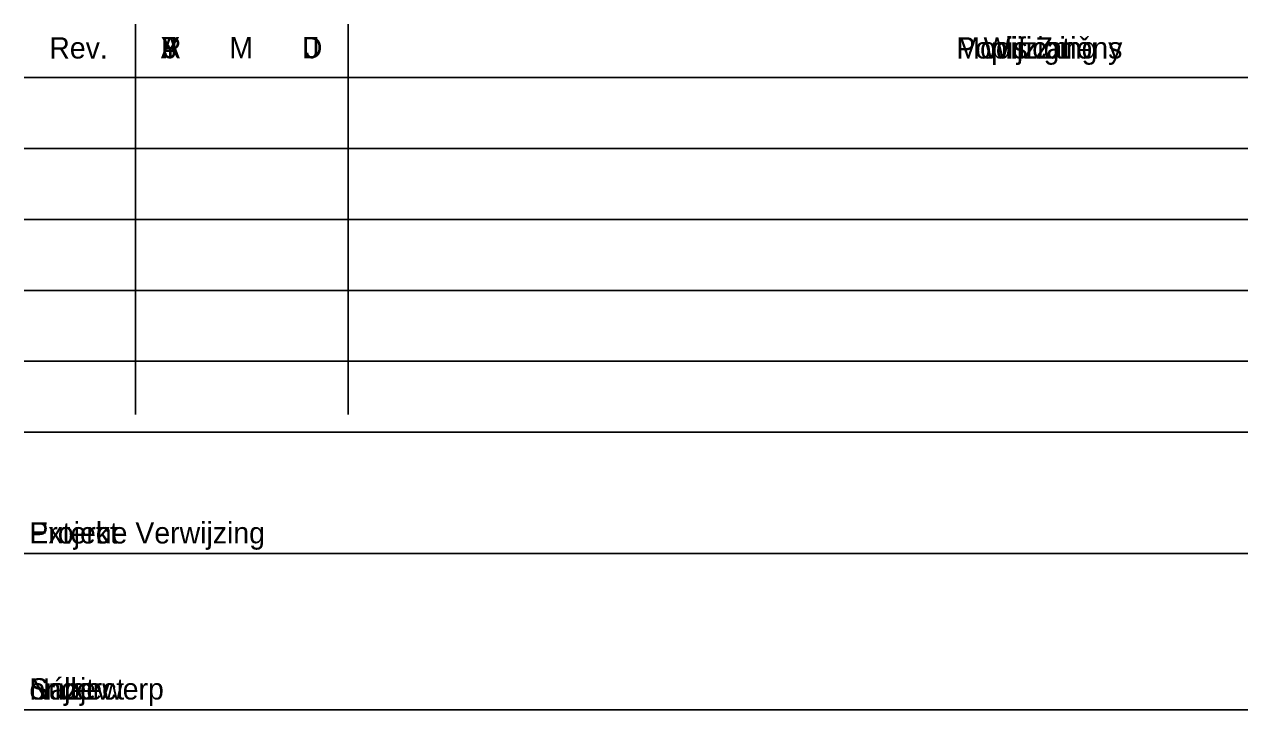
# Model space of a CAD drawing. Extents: x -781661 to -760591, y -1008188 to -975620.
# Drawn here: x -781639.17 to -781630.6, y -1008177.45 to -1008172.62 of the extents above; entities that cross this region are included whole.
import ezdxf

# ---------------------------------------------------------------- set-up
doc = ezdxf.new("R2010")
doc.units = 0
for name, color, linetype in [('Border', 7, 'Continuous'), ('Border_TextCZ', 7, 'Continuous'), ('Border_TextFR', 7, 'Continuous'), ('Border_TextNL', 7, 'Continuous'), ('Border_TextUK', 7, 'Continuous')]:
    doc.layers.add(name, color=color, linetype=linetype)

# ---------------------------------------------------------------- blocks, each defined once
blk = doc.blocks.new('A3coversheet_v03_CZ_1_1')
at = {"layer": 'Border'}
blk.add_line((2.19583, 1.52058), (4.09583, 1.52058), dxfattribs=at)
for points in [[(2.27417, 1.55808), (2.27417, 1.28308)], [(2.42417, 1.55808), (2.42417, 1.28308)], [(2.19583, 1.52058), (4.10417, 1.52058)], [(2.19583, 1.47058), (4.10417, 1.47058)], [(2.19583, 1.42058), (4.10417, 1.42058)], [(2.19583, 1.37058), (4.10417, 1.37058)], [(2.19583, 1.32058), (4.10417, 1.32058)], [(2.19583, 1.27058), (4.10417, 1.27058)], [(2.19583, 1.18503), (4.10417, 1.18503)], [(2.19583, 1.07503), (4.10417, 1.07503)]]:
    blk.add_lwpolyline(points, dxfattribs=at)
at = {"layer": 'Border_TextCZ'}
for s, p in [('Rev.', (2.21345, 1.53396)), ('R', (2.29212, 1.5341)), ('M', (2.34039, 1.5341)), ('D', (2.39155, 1.5341)), ('Popis Změny', (2.85302, 1.53396)), ('Projekt', (2.19942, 1.19219)), ('Název', (2.19942, 1.08219))]:
    blk.add_text(s, height=0.015, dxfattribs=at).set_placement(p)
at = {"layer": 'Border_TextFR'}
for s, p in [('Rev.', (2.21345, 1.53396)), ('A', (2.29212, 1.5341)), ('M', (2.34039, 1.5341)), ('J', (2.39388, 1.5341)), ('Modifications', (2.85301, 1.53396)), ('Projet', (2.19942, 1.19219)), ('Sujet', (2.19942, 1.08219))]:
    blk.add_text(s, height=0.015, dxfattribs=at).set_placement(p)
at = {"layer": 'Border_TextNL'}
for s, p in [('Rev.', (2.21345, 1.53396)), ('J', (2.29388, 1.5341)), ('M', (2.34039, 1.5341)), ('D', (2.39155, 1.5341)), ('Wijziging', (2.87223, 1.53396)), ('Externe Verwijzing', (2.19942, 1.19219)), ('onderwerp', (2.19942, 1.08219))]:
    blk.add_text(s, height=0.015, dxfattribs=at).set_placement(p)
at = {"layer": 'Border_TextUK'}
for s, p in [('Rev.', (2.21345, 1.53396)), ('Y', (2.29212, 1.5341)), ('M', (2.34039, 1.5341)), ('D', (2.39155, 1.5341)), ('Modifications', (2.85301, 1.53396)), ('Project', (2.19942, 1.19219)), ('Subject', (2.19942, 1.08219))]:
    blk.add_text(s, height=0.015, dxfattribs=at).set_placement(p)

msp = doc.modelspace()

# ---------------------------------------------------------------- block references
at = {"layer": 'Border', "xscale": 10.0000000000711, "yscale": 10.0000000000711, "rotation": -5.594541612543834e-09}
msp.add_blockref('A3coversheet_v03_CZ_1_1', (-781661.1304, -1008188.198), dxfattribs=at)

doc.saveas('drawing.dxf')
